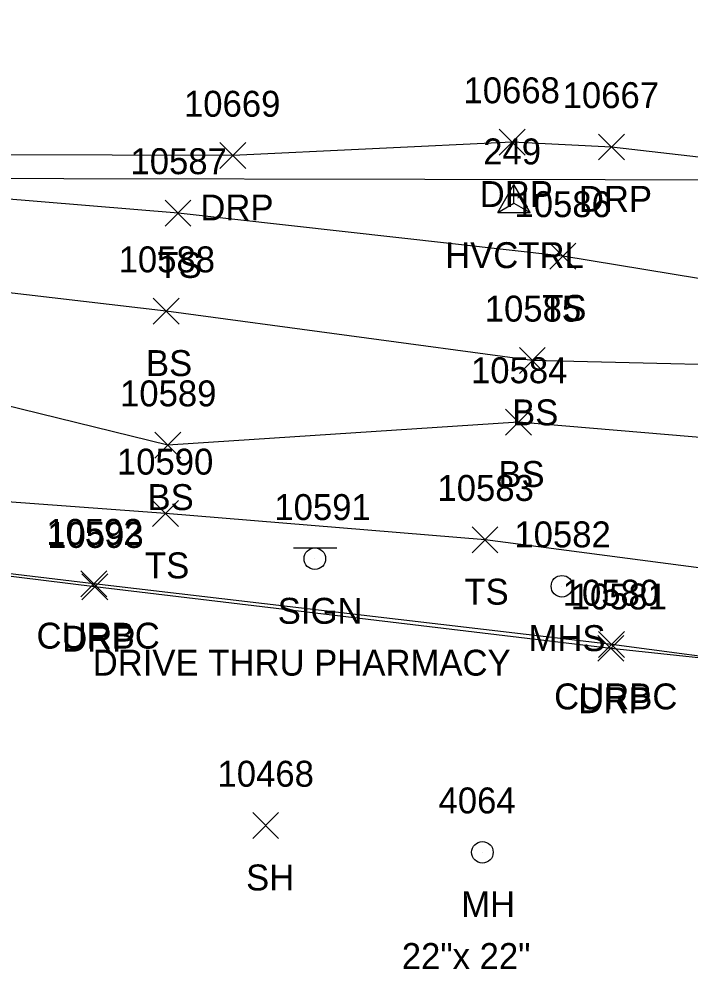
# Model space of a CAD drawing. Extents: x 1769141 to 1770911, y 735471 to 741449.
# Drawn here: x 1770501.4 to 1770553.2, y 738814 to 738887.2 of the extents above; entities that cross this region are included whole.
import ezdxf

# ---------------------------------------------------------------- set-up
doc = ezdxf.new("R2010")
doc.units = 0
for name, color, linetype in [('C_A', 7, 'Continuous'), ('C_I', 7, 'Continuous'), ('CPSM', 7, 'Continuous'), ('DCP', 7, 'Continuous'), ('L_A', 7, 'Continuous'), ('L_I', 7, 'Continuous'), ('L_TIC', 7, 'Continuous'), ('LELB', 7, 'Continuous'), ('R_A', 7, 'Continuous'), ('R_I', 7, 'Continuous'), ('R_TIC', 7, 'Continuous'), ('RC', 7, 'Continuous'), ('RDP', 7, 'Continuous'), ('S_A', 7, 'Continuous'), ('S_C', 7, 'Continuous'), ('S_I', 7, 'Continuous'), ('SSGN', 7, 'Continuous'), ('U_A', 7, 'Continuous'), ('U_C', 7, 'Continuous'), ('U_I', 7, 'Continuous'), ('USMH', 7, 'Continuous'), ('UUMH', 7, 'Continuous')]:
    doc.layers.add(name, color=color, linetype=linetype)

msp = doc.modelspace()

# ---------------------------------------------------------------- linework, layer by layer
at = {"layer": 'CPSM'}
for p, q in [((1770538.362, 738872.295), (1770539.612, 738874.46)), ((1770540.862, 738872.295), (1770539.612, 738874.46)), ((1770539.613, 738873.017), (1770539.612, 738874.46)), ((1770538.362, 738872.295), (1770539.613, 738873.017)), ((1770539.613, 738873.017), (1770539.613, 738873.017)), ((1770539.613, 738873.017), (1770540.862, 738872.295)), ((1770538.362, 738872.295), (1770540.862, 738872.295))]:
    msp.add_line(p, q, dxfattribs=at)
at = {"layer": 'DCP'}
msp.add_lwpolyline([(1770588.409, 738874.754), (1770449.176, 738875.006)], dxfattribs=at)
at = {"layer": 'L_TIC'}
for points in [[(1770512.698, 738871.263), (1770514.698, 738873.263)], [(1770514.698, 738871.263), (1770512.698, 738873.263)], [(1770542.38, 738867.949), (1770544.38, 738869.949)], [(1770544.38, 738867.949), (1770542.38, 738869.949)], [(1770511.782, 738863.692), (1770513.782, 738865.692)], [(1770513.782, 738863.692), (1770511.782, 738865.692)], [(1770540.031, 738859.892), (1770542.031, 738861.892)], [(1770542.031, 738859.892), (1770540.031, 738861.892)], [(1770538.969, 738855.139), (1770540.969, 738857.139)], [(1770540.969, 738855.139), (1770538.969, 738857.139)], [(1770511.902, 738853.356), (1770513.902, 738855.356)], [(1770513.902, 738853.356), (1770511.902, 738855.356)], [(1770511.739, 738848.091), (1770513.739, 738850.091)], [(1770513.739, 738848.091), (1770511.739, 738850.091)], [(1770536.382, 738846.063), (1770538.382, 738848.063)], [(1770538.382, 738846.063), (1770536.382, 738848.063)], [(1770519.46, 738824.022), (1770521.46, 738826.022)], [(1770521.46, 738824.022), (1770519.46, 738826.022)]]:
    msp.add_lwpolyline(points, dxfattribs=at)
at = {"layer": 'LELB'}
for points in [[(1770580.789, 738863.858), (1770564.485, 738865.47), (1770543.38, 738868.949), (1770513.698, 738872.263), (1770461.134, 738876.605), (1770422.074, 738880.143), (1770383.419, 738886.534), (1770350.123, 738889.47), (1770337.617, 738892.523), (1770340.946, 738915.919), (1770342.098, 738948.843), (1770346.552, 738996.467), (1770341.404, 739000.599), (1770372.716, 739000.929), (1770395.171, 738998.489)], [(1770576.974, 738855.588), (1770564.552, 738860.337), (1770541.031, 738860.892), (1770512.782, 738864.692), (1770460.849, 738870.771), (1770421.538, 738877.167), (1770380.978, 738877.161), (1770329.126, 738870.56)], [(1770575.427, 738851.507), (1770564.618, 738854.063), (1770539.969, 738856.139), (1770512.902, 738854.356), (1770460.497, 738867.228), (1770420.361, 738870.08), (1770379.594, 738871.187), (1770330.707, 738861.726)], [(1770560.33, 738844.066), (1770537.382, 738847.063), (1770512.739, 738849.091), (1770458.643, 738853.08), (1770418.828, 738857.317), (1770378.62, 738862.152), (1770363.306, 738861.947), (1770348.445, 738856.662), (1770336.441, 738849.215), (1770320.849, 738835.083), (1770307.153, 738828.306)]]:
    msp.add_lwpolyline(points, dxfattribs=at)
at = {"layer": 'R_TIC'}
for points in [[(1770538.486, 738876.73), (1770540.486, 738878.73)], [(1770540.486, 738876.73), (1770538.486, 738878.73)], [(1770546.134, 738876.358), (1770548.134, 738878.358)], [(1770548.134, 738876.358), (1770546.134, 738878.358)], [(1770516.931, 738875.693), (1770518.931, 738877.693)], [(1770518.931, 738875.693), (1770516.931, 738877.693)], [(1770506.197, 738842.671), (1770508.197, 738844.671)], [(1770508.197, 738842.671), (1770506.197, 738844.671)], [(1770506.276, 738842.44), (1770508.276, 738844.44)], [(1770508.276, 738842.44), (1770506.276, 738844.44)], [(1770546.132, 738837.985), (1770548.132, 738839.985)], [(1770548.132, 738837.985), (1770546.132, 738839.985)], [(1770546.09, 738837.693), (1770548.09, 738839.693)], [(1770548.09, 738837.693), (1770546.09, 738839.693)]]:
    msp.add_lwpolyline(points, dxfattribs=at)
at = {"layer": 'RC'}
msp.add_lwpolyline([(1770559.141, 738837.402), (1770547.132, 738838.985), (1770507.197, 738843.671), (1770457.96, 738849.563), (1770418.242, 738854.425), (1770378.005, 738859.227), (1770369.759, 738859.38)], dxfattribs=at)
at = {"layer": 'RDP'}
for points in [[(1770603.252, 738853.259), (1770597.442, 738860.218), (1770584.218, 738869.599), (1770576.318, 738873.126), (1770564.371, 738875.354), (1770547.134, 738877.358), (1770539.486, 738877.73), (1770517.931, 738876.693), (1770489.986, 738876.775), (1770463.101, 738878.98), (1770429.892, 738883.978), (1770384.524, 738891.181), (1770390.254, 738926.77), (1770396.424, 738962.601), (1770401.148, 738990.561), (1770408.495, 739034.938), (1770412.752, 739059.9), (1770415.704, 739078.025), (1770420.835, 739077.401)], [(1770559.141, 738837.402), (1770547.09, 738838.693), (1770507.276, 738843.44), (1770458.059, 738849.503), (1770418.211, 738854.176), (1770378.128, 738859.017), (1770369.697, 738859.155)]]:
    msp.add_lwpolyline(points, dxfattribs=at)
at = {"layer": 'SSGN'}
for p, q in [((1770522.605, 738846.44), (1770525.938, 738846.44)), ((1770524.252, 738845.607), (1770524.252, 738845.607))]:
    msp.add_line(p, q, dxfattribs=at)
msp.add_circle((1770524.252, 738845.607), 0.833, dxfattribs=at)
at = {"layer": 'USMH'}
for p, q in [((1770543.317, 738843.481), (1770543.317, 738843.481)), ((1770544.15, 738843.481), (1770544.15, 738843.481))]:
    msp.add_line(p, q, dxfattribs=at)
msp.add_circle((1770543.317, 738843.481), 0.833, dxfattribs=at)
at = {"layer": 'UUMH'}
for p, q in [((1770537.181, 738822.963), (1770537.181, 738822.963)), ((1770538.014, 738822.963), (1770538.014, 738822.963))]:
    msp.add_line(p, q, dxfattribs=at)
msp.add_circle((1770537.181, 738822.963), 0.833, dxfattribs=at)

# ---------------------------------------------------------------- texts
at = {"layer": 'C_A'}
msp.add_text('HVCTRL', height=2, dxfattribs=at).set_placement((1770534.306, 738868.017))
at = {"layer": 'C_I'}
msp.add_text('249', height=2, dxfattribs=at).set_placement((1770537.243, 738876.017))
at = {"layer": 'L_A'}
for s, p in [('TS', (1770512.108, 738867.263)), ('TS', (1770541.79, 738863.949)), ('BS', (1770511.223, 738859.692)), ('BS', (1770539.472, 738855.892)), ('BS', (1770538.41, 738851.139)), ('BS', (1770511.343, 738849.356)), ('TS', (1770511.149, 738844.091)), ('TS', (1770535.791, 738842.063)), ('SH', (1770518.948, 738820.022))]:
    msp.add_text(s, height=2, dxfattribs=at).set_placement(p)
at = {"layer": 'L_I'}
for s, p in [('10587', (1770510.029, 738875.263)), ('10586', (1770539.656, 738871.949)), ('10588', (1770509.113, 738867.692)), ('10585', (1770537.362, 738863.892)), ('10584', (1770536.3, 738859.139)), ('10589', (1770509.225, 738857.356)), ('10590', (1770508.983, 738852.091)), ('10583', (1770533.712, 738850.063)), ('10468', (1770516.743, 738828.022))]:
    msp.add_text(s, height=2, dxfattribs=at).set_placement(p)
at = {"layer": 'R_A'}
for s, p in [('DRP', (1770536.974, 738872.73)), ('DRP', (1770544.622, 738872.358)), ('DRP', (1770515.419, 738871.693)), ('CURBC', (1770502.78, 738838.671)), ('DRP', (1770504.765, 738838.44)), ('CURBC', (1770542.715, 738833.985)), ('DRP', (1770544.578, 738833.693))]:
    msp.add_text(s, height=2, dxfattribs=at).set_placement(p)
at = {"layer": 'R_I'}
for s, p in [('10668', (1770535.722, 738880.73)), ('10667', (1770543.37, 738880.358)), ('10669', (1770514.159, 738879.693)), ('10592', (1770503.528, 738846.671)), ('10593', (1770503.607, 738846.44)), ('10580', (1770543.376, 738841.985)), ('10581', (1770543.987, 738841.693))]:
    msp.add_text(s, height=2, dxfattribs=at).set_placement(p)
at = {"layer": 'S_A'}
msp.add_text('SIGN', height=2, dxfattribs=at).set_placement((1770521.389, 738840.587))
at = {"layer": 'S_C'}
msp.add_text('DRIVE THRU PHARMACY', height=2, dxfattribs=at).set_placement((1770507.114, 738836.587))
at = {"layer": 'S_I'}
msp.add_text('10591', height=2, dxfattribs=at).set_placement((1770521.13, 738848.587))
at = {"layer": 'U_A'}
for s, p in [('MHS', (1770540.734, 738838.481)), ('MH', (1770535.543, 738817.963))]:
    msp.add_text(s, height=2, dxfattribs=at).set_placement(p)
at = {"layer": 'U_C'}
msp.add_text('22"x 22"', height=2, dxfattribs=at).set_placement((1770530.961, 738813.963))
at = {"layer": 'U_I'}
for s, p in [('10582', (1770539.648, 738846.481)), ('4064', (1770533.795, 738825.963))]:
    msp.add_text(s, height=2, dxfattribs=at).set_placement(p)

doc.saveas('drawing.dxf')
